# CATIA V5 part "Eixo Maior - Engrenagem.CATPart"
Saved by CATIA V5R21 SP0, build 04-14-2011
Part number: Eixo Maior - Engrenagem
Definition: Eixo Maior - Engrenagem
Nomenclature: Eixo Maior - Engrenagem
Source: Unknown
Bounding box of the stored display mesh (mm): x -0.45 to 0.45, y 0 to 8.8, z -0.45 to 0.45
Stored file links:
  C:\Users\beatr\OneDrive\Documents\UNB\2026_1\Pi1\Componentes eletronicos\Eixo Maior - Engrenagem.CATPart
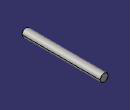
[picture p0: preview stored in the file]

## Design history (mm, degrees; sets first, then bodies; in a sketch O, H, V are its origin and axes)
Body1 "Sólido1" (main body)
  Solid1: solid without history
